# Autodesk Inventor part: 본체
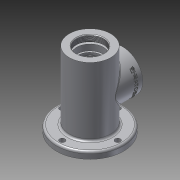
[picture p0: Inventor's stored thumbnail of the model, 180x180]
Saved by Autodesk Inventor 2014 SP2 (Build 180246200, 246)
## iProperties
Created: 2016-08
Part Number: 본체
Material: 알루미늄 6061
Document SubType Name: Modeling
Designer: 201-01
Density: 2.71 g/cm^3
Appearance: 알루미늄 - 평지
Mass: 730.302 g
Surface Area: 615.466 cm^2
Volume: 269.484 cm^3
Author: 201-01
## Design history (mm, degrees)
sketch "스케치1"
  geometry: C1 r 31 at (0, 0); 1 further point
  constraints: 1 centre point, 1 coincident
  dimensions: "d0" = 62 diameter of C1
extrude "돌출1" new body sketch "스케치1" distance "d1" = 102; taper "d2" = 0 deg
sketch "스케치2"
  geometry: C1 r 50 at (0, 0); 1 further point
  constraints: 1 centre point, 1 coincident
  dimensions: "d3" = 100 diameter of C1
extrude "돌출2" join sketch "스케치2" distance "d4" = 10; taper "d5" = 0 deg
sketch "스케치3"
  geometry: C1 r 31 at (0, 0); 1 further point
  constraints: 1 centre point, 1 coincident
  dimensions: "d6" = 62 diameter of C1
extrude "돌출3" join sketch "스케치3" distance "d7" = 3; taper "d8" = 0 deg
node "작업 평면1"
sketch "스케치4"
  geometry: L1 (31, 0)-(31, 102) reference; L2 (31, 102)-(-31, 102) reference; L3 (-31, 0)-(-31, 102) reference; L4 (50, 0)-(-50, 0) reference; C1 r 30 at (0, 46); 1 further point
  constraints: 1 centre point
  dimensions: "d10" = 60 diameter of C1; "d11" = 56 distance from line of L2 C1.centre; "d12" = 31 distance from line of L1 C1.centre
extrude "돌출4" join sketch "스케치4" stored distance "d13" = 3; taper "d14" = 0 deg
sketch "스케치5"
  geometry: 2 further points
  constraints: 1 coincident
hole "구멍1" sketch "스케치5" at (0, 0) diameter "d15" = 40.376; stored, may be unused: countersink angle "d19" = 90 deg, drill point angle "d21" = 0 deg; dims "d16" = 9, "d17" = 4, "d18" = 2, "d20" = 9
sketch "스케치6"
  geometry: C1 r 24 at (0, 0); 1 further point
  constraints: 1 centre point, 1 coincident
  dimensions: "d22" = 48 diameter of C1
extrude "돌출5" cut sketch "스케치6" distance "d23" = 3; taper "d24" = 0 deg
sketch "스케치11"
  geometry: C1 r 20 at (0, 0); 1 further point
  constraints: 1 centre point, 1 coincident
  dimensions: "d37" = 40 diameter of C1
extrude "돌출10" cut sketch "스케치11" distance "d38" = 9; taper "d39" = 0 deg
sketch "스케치12"
  geometry: C1 r 17.5 at (0, 0); 1 further point
  constraints: 1 centre point, 1 coincident
  dimensions: "d40" = 35 diameter of C1
extrude "돌출11" cut sketch "스케치12" distance "d41" = 3.25; taper "d42" = 0 deg
sketch "스케치13"
  geometry: C1 r 18.5 at (0, 0); 1 further point
  constraints: 1 centre point, 1 coincident
  dimensions: "d43" = 37 diameter of C1
extrude "돌출12" cut sketch "스케치13" distance "d44" = 1.75; taper "d45" = 0 deg
sketch "스케치14"
  geometry: C1 r 17.5 at (0, 0); 1 further point
  constraints: 1 centre point, 1 coincident
  dimensions: "d46" = 35 diameter of C1
extrude "돌출13" cut sketch "스케치14" distance "d47" = 11; taper "d48" = 0 deg
sketch "스케치15"
  geometry: C1 r 26 at (0, 0); 1 further point
  constraints: 1 centre point, 1 coincident
  dimensions: "d49" = 52 diameter of C1
extrude "돌출14" cut sketch "스케치15" distance "d50" = 38; taper "d51" = 0 deg
sketch "스케치16"
  geometry: C1 r 17.5 at (0, 0); 1 further point
  constraints: 1 centre point, 1 coincident
  dimensions: "d52" = 35 diameter of C1
extrude "돌출15" cut sketch "스케치16" distance "d53" = 11; taper "d54" = 0 deg
sketch "스케치17"
  geometry: C1 r 16.5 at (0, 0); 1 further point
  constraints: 1 centre point, 1 coincident
  dimensions: "d55" = 33 diameter of C1
extrude "돌출16" cut sketch "스케치17" distance "d56" = 5; taper "d57" = 0 deg
sketch "스케치18"
  geometry: C1 r 10 at (0, 0); 1 further point
  constraints: 1 centre point, 1 coincident
  dimensions: "d58" = 20 diameter of C1
extrude "돌출17" cut sketch "스케치18" distance "d59" = 2.7; taper "d60" = 0 deg
sketch "스케치19"
  geometry: C1 r 12.5 at (0, 0); 1 further point
  constraints: 1 centre point, 1 coincident
  dimensions: "d61" = 25 diameter of C1
extrude "돌출18" cut sketch "스케치19" distance "d62" = 7.3; taper "d63" = 0 deg
sketch "스케치20"
  geometry: C1 r 30 at (0, 0) reference; C2 r 19 at (0, 0); 1 further point
  constraints: 1 centre point, 1 coincident
  dimensions: "d64" = 38 diameter of C2
extrude "돌출19" cut sketch "스케치20" stored distance "d65" = 7.3; taper "d66" = 0 deg
sketch "스케치21"
  geometry: C1 r 19 at (0, 0) reference; 2 further points
  dimensions: "d67" = 24 distance of C1.centre point (0, 24)
hole "구멍2" sketch "스케치21" at (0, 24) diameter "d68" = 3.242; stored, may be unused: countersink angle "d72" = 90 deg, drill point angle "d74" = 0 deg; dims "d69" = 8, "d70" = 4, "d71" = 2, "d73" = 10
sketch "스케치22"
  geometry: C1 r 4 at (0, 41.5); 1 further point
  constraints: 1 centre point
  dimensions: "d78" = 8 diameter of C1; "d79" = 41.5 distance of point (0, 0) C1.centre
extrude "돌출20" cut sketch "스케치22" stored distance "d80" = 7.3; taper "d81" = 0 deg
node "작업 평면2"
sketch "스케치23"
  geometry: L1 (35.449, 66.739)-(35.449, 25.261); L2 (35.449, 25.261)-(42.551, 25.261); L3 (42.551, 25.261)-(42.551, 66.739); L4 (42.551, 66.739)-(35.449, 66.739); L5 (31, 102)-(-31, 102) reference; L6 (49, 76)-(49, 16) reference; 4 further points
  constraints: 2 midpoint, 1 horizontal alignment, 1 vertical alignment, 2 other
  dimensions: "d86" = 56 distance from line of L5 point (39, 46); "d87" = 10 distance from line of point (39, 46) L6
feature "엠보싱1" sketch "스케치23" dims "d0" = 62, "d88" = 0.5, "d89" = 0
chamfer "모따기1" distance "d90" = 1; stored, may be unused: second distance "d91" = 2, angle "d92" = 45 deg
chamfer "모따기2" distance "d93" = 1; stored, may be unused: second distance "d94" = 2, angle "d95" = 45 deg
chamfer "모따기3" distance "d96" = 1; stored, may be unused: second distance "d97" = 2, angle "d98" = 45 deg
fillet "모깎기1" dims "d99" = 0.3
fillet "모깎기2" dims "d100" = 3
fillet "모깎기3" dims "d101" = 3
sketch "스케치24"
  geometry: C1 r 16 at (0, 0); 1 further point
  constraints: 1 centre point, 1 coincident
  dimensions: "d102" = 32 diameter of C1
extrude "돌출21" cut sketch "스케치24" stored distance "d103" = 7.3; taper "d104" = 20 deg
fillet "모깎기4" dims "d105" = 3
chamfer "모따기4" distance "d106" = 0.7; stored, may be unused: second distance "d107" = 2, angle "d108" = 60 deg
fillet "모깎기6" dims "d110" = 3
node "솔리드1"
pattern_circular "원형 패턴1" dims angle "d76" = 360 deg
pattern_circular "원형 패턴2" dims angle "d83" = 360 deg
other parameters: "d9" = 49, "d85" = 31
